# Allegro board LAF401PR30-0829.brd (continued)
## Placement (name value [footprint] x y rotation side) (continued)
PR603  0_0402_5%  [R0402_0OHM]  72.6 46.85 0 bottom
PR604  75_0402_1%  [R_0402]  73.76 49.92 0 bottom
PR605  100_0402_1%  [R_0402]  73.76 49.03 0 bottom
PR606  0_0402_5%  [R0402_0OHM]  69.42 88.41 180 bottom
PR608  88.7K_0402_1%  [R_0402]  73.42 47.11 270 top
PR610  10K_0402_1%  [R_0402]  72.22 56.15 270 top
PR611  1.87K +-1% 0402  [R_0402]  71.63 46.21 0 top
PR612  1.91K_0402_1%  [R_0402]  74.68 52.57 180 bottom
PR613  90.9K +-1% 0402  [R_0402]  71.25 52.34 90 bottom
PR614  0_0402_5%  [R0402_0OHM]  74.68 51.68 180 bottom
PR615  0_0402_5%  [R_0402]  64.2 55.19 90 top
PR616  0_0402_5%  [R0402_0OHM]  74.44 53.49 180 top
PR617  4.3K_0402_1%  [R_0402]  68.25 53.28 0 bottom
PR618  49.9_0402_1%  [R_0402]  74.63 50.82 180 top
PR619  2.2_0603_5%  [R_0603]  66.3 85.62 270 bottom
PR620  0_0402_5%  [R0402_0OHM]  73.1 55.63 270 top
PR621  316_0402_1%  [R_0402]  70.42 56.98 270 top
PR622  1.91K_0402_1%  [R_0402]  69.55 56.99 270 top
PR623  2K_0402_1%  [R_0402]  70.44 55.2 180 top
PR624  3.65K_0603_1%  [R_0603]  78.81 85.62 270 top
PR625  0_0402_5%  [R0402_0OHM]  74.43 49.92 180 top
PR626  10_0402_1%  [R_0402]  74.25 49.04 180 top
PR627  4.7_1206_5%  [R_1206]  76.97 86.06 180 top
PR628  4.99K_0402_1%  [R_0402]  69.52 56.09 0 bottom
PR629  88.7K_0402_1%  [R_0402]  66.5 51.8 180 bottom
PR630  2.49K_0402_1%  [R_0402]  70.84 47.2 0 bottom
PR631  27.4K_0402_1%  [R_0402]  71.3 57.4 0 top
PR632  1K_0402_1%  [R_0402]  66.88 56.98 180 top
PR633  11K_0402_1%  [R_0402]  67.77 55.18 90 bottom
PR634  0_0402_5%  [R_0402]  65.09 55.19 90 top
PR635  10K_0402_1%  [R_0402]  65.59 49.12 90 bottom
PR636  604_0402_1%  [R_0402]  71.77 43.9 0 top
PR638  374_0402_1%  [R_0402]  66.87 56.1 270 top
PR639  3.09K_0402_1%  [R_0402]  64.14 47.21 90 bottom
PR640  365_0402_1%  [R_0402]  62.8 47 180 top
PR641  1K_0402_1%  [R_0402]  73.57 44.79 270 top
PR642  2.61K_0402_1%  [R_0402]  81.4 83.01 0 top
PR643  11K_0402_1%  [R_0402]  72.67 43.05 270 top
PR644  1K_0402_1%  [R_0402]  61.03 46.09 90 top
PR645  316_0402_1%  [R_0402]  60.95 53.49 0 top
PR646  316_0402_1%  [R_0402]  67.1 43.83 270 bottom
PR647  27.4K_0402_1%  [R_0402]  66.47 50.03 270 bottom
PR648  1.91K_0402_1%  [R_0402]  62.74 51.82 90 top
PR649  1.62K_0402_1%  [R_0402]  67.08 44.68 0 bottom
PR650  2K_0402_1%  [R_0402]  62.74 53.6 90 top
PR651  113K_0402_1%  [R_0402]  68.06 47.07 90 bottom
PR652  2K_0402_1%  [R_0402]  66.24 44.7 270 bottom
PR653  20M_0402_5%  [R_0402]  60.01 50.89 270 top
PR656  11K_0402_1%  [R_0402]  61.04 48.76 270 top
PR657  4.42K_0402_1%  [R_0402]  60.17 49.1 180 top
PR658  20M_0402_5%  [R_0402]  68.65 56.1 270 bottom
PR659  0_0402_5%  [R0402_0OHM]  62.12 72.28 0 top
PR660  3.9_0603_1%  [R_0603]  53.59 71.04 0 bottom
PR661  3.65K_0603_1%  [R_0603]  58.7 48.05 0 top
PR662  0_0402_5%  [R0402_0OHM]  54.31 58.9 0 bottom
PR663  4.7_1206_5%  [R_1206]  64.69 71.52 270 top
PR664  0_0402_5%  [R0402_0OHM]  54.31 58.03 0 bottom
PR665  3.9_0603_1%  [R_0603]  54.37 61.66 0 bottom
PR666  10_0402_1%  [R_0402]  68.25 73.3 0 top
PR667  3.65K_0603_1%  [R_0603]  67.7 72.34 270 top
PR668  100K_0402_1%  [R_0402]  66.62 70.93 90 top
PR669  4.7_1206_5%  [R_1206]  67.02 66.95 180 top
PR670  100K_0402_1%  [R_0402]  71.3 58.29 0 top
PR671  0_0402_5%  [R_0402]  62.21 76.14 0 bottom
PR672  3.9_0603_1%  [R_0603]  63.06 77.62 0 top
PR673  10_0402_1%  [R_0402]  72.22 57.8 180 bottom
PR674  3.65K_0603_1%  [R_0603]  68.97 72.34 270 top
PR675  100K_0402_1%  [R_0402]  68.98 70 180 top
PR676  4.7_1206_5%  [R_1206]  71.76 78.43 270 top
PR677  100K_0402_1%  [R_0402]  68.98 69.11 180 top
PR678  100_0402_1%  [R_0402]  73.56 51.69 90 top
PR679  0_0402_5%  [R0402_0OHM]  68.22 83.58 180 bottom
PR680  1_0603_5%  [R_0603]  57.33 59.89 90 top
PR681  10K_0402_1%  [R_0402]  57.74 58.79 180 top
PR682  -  [SOLDER_PREFORMS_0603]  112.16 62.76 180 top
PR683  -  [SOLDER_PREFORMS_0603]  107.69 62.76 0 top
PR684  -  [SOLDER_PREFORMS_0603]  112.73 56.98 180 top
PR686  10K_0402_1%  [R_0402]  57.94 69.18 270 top
PR687  0_0402_5%  [R0402_0OHM]  57.18 68.27 90 top
PR688  1_0603_5%  [R_0603]  57.43 70.06 90 top
PR689  10K_0402_1%  [R_0402]  65.33 75.02 180 top
PR691  1_0603_5%  [R_0603]  64.44 76.24 180 top
PR692  0_0402_5%  [R_0402]  62.21 75.38 0 bottom
PR901  0.01_1206_1%  [R_1206_4P-D]  5.48 18.26 270 bottom
PR909  2_0603_1%  [R_0603]  14.06 22.09 0 top
PR910  2_0603_1%  [R_0603]  14.06 23.34 0 top
PR914  3.3_0603_1%  [R_0603]  19.56 21.93 90 top
PR915  4.7_0603_5%  [R_0603]  20.34 18.81 180 bottom
PR916  1_0805_5%~D  [R_0805]  12.29 21.8 180 top
PR917  0.005_1206_1%  [R_1206_4P-D]  29.74 11.13 270 top
PR918  100K_0402_1%  [R_0402]  12.37 19.58 0 bottom
PR919  0_0402_5%  [R_0402]  13.21 18.57 270 top
PR920  0_0402_5%  [R0402_0OHM]  12.29 16.73 0 top
PR921  4.7_0603_5%  [R_0603]  22.87 17.93 0 top
PR922  0_0402_5%  [R0402_0OHM]  12.29 15.84 0 top
PR923  4.7_1206_5%  [R_1206]  17.1 25.98 90 top
PR924  4.7_1206_5%  [R_1206]  28.45 23.7 0 top
PR925  154K_0402_1%  [R_0402]  33.66 32.58 90 top
PR926  0_0402_5%  [R0402_0OHM]  12.29 14.79 0 top
PR927  1M_0402_1%  [R_0402]  37.79 32.45 90 top
PR928  0_0402_5%  [R0402_0OHM]  12.29 13.92 0 top
PR929  0_0402_5%  [R0402_0OHM]  22.71 18.5 0 bottom
PR930  100K_0402_1%  [R_0402]  13.55 11.56 180 top
PR931  100K_0402_1%  [R_0402]  12.65 10.7 0 top
PR932  105K_0402_1%  [R_0402]  17.73 14.88 180 bottom
PR933  100K_0402_1%  [R_0402]  15.54 11.47 90 top
PR934  499_0402_1%  [R_0402]  16.4 12.39 270 top
PR935  0_0402_5%  [R0402_0OHM]  18.17 9.16 0 top
PR936  0_0402_5%  [R0402_0OHM]  19.11 12.39 270 top
PR937  1_0603_1%  [R_0603]  23.44 14.56 0 top
PR938  1_0603_1%  [R_0603]  23.44 13.3 0 top
PR939  0_0402_5%  [R0402_0OHM]  36.85 30.12 180 top
PR940  100_0402_5%  [R_0402]  21.87 11.49 90 top
PR941  0_0402_5%  [R0402_0OHM]  33.9 28.09 0 top
PR942  0_0402_5%  [R0402_0OHM]  34.37 31.64 180 top
PR943  0_0603_5%  [R_0603]  13.66 20.59 0 top
PR944  442K_0402_1%  [R_0402]  12.37 16.02 0 bottom
PR945  100K_0402_5%  [R_0402]  13.29 17.8 180 bottom
PR946  0_0402_5%  [R0402_0OHM]  30.03 33.36 0 top
PR947  0_0402_5%  [R0402_0OHM]  18.17 8.27 0 top
PR948  12.7K_0402_1%  [R_0402]  20.07 12.39 270 top
PR950  0_0402_5%  [R_0402]  32.52 28.86 270 top
PR951  0_0402_5%  [R0402_0OHM]  14.61 11.45 90 top
PR953  100K_0402_1%  [R_0402]  31.81 33.36 0 top
PR960  0_0402_5%  [R0402_0OHM]  12.32 18.57 270 top
PR961  100K_0402_1%  [R_0402]  31.63 29.94 270 top
PR1201  240K_0402_1%  [R_0402]  67.2 111.31 270 top
PR1202  300K_0402_5%  [R_0402]  4.2 39.23 90 top
PR1203  1.8M_0402_1%  [R_0402]  68.1 109.14 180 top
PR1205  499K_0402_1%  [R_0402]  7.75 51.58 270 top
PR1206  1K_0402_1%  [R_0402]  64.54 109.59 0 bottom
PR1207  499K_0402_1%  [R_0402]  9.39 41.72 0 top
PR1208  102K_0402_1%  [R_0402]  66.42 112.18 270 bottom
PR1209  100K_0402_5%  [R_0402]  3.22 40.12 270 top
PR1210  1M_0402_5%  [R_0402]  12.57 37.67 0 top
PR1211  0_0402_5%  [R0402_0OHM]  18.03 37.73 0 top
PR1212  49.9K_0402_1%  [R_0402]  3.64 49.36 180 top
PR1213  49.9K_0402_1%  [R_0402]  10.29 40.66 270 top
PR1214  100K_0402_5%  [R_0402]  18.3 31.83 180 top
PR1215  0_0402_5%  [R0402_0OHM]  23.25 33.93 90 top
PR1216  0_0402_5%  [R0402_0OHM]  17.15 33.63 180 top
PR1217  84.5K_0402_1%  [R_0402]  67.32 112.16 0 bottom
PR1218  0_0402_5%  [R0402_0OHM]  16.46 31.78 90 top
PR1219  23.2K_0402_1%  [R_0402]  68.07 111.27 0 top
PR1220  0_0402_5%  [R0402_0OHM]  16.21 37.61 180 top
PR1221  0_0402_5%  [R0402_0OHM]  21.34 34.44 0 top
PR1222  100K_0402_5%  [R_0402]  16.21 38.5 180 top
PR1223  0_0402_5%  [R0402_0OHM]  13.44 31.11 0 top
PR1224  100K_0402_5%  [R_0402]  22.23 35.32 90 top
PR1225  0_0402_5%  [R0402_0OHM]  21.19 30.88 0 top
PR1226  100K_0402_5%  [R_0402]  23.25 32.02 90 top
PR1227  100K_0402_5%  [R_0402]  16.64 85.11 270 top
PR1228  499K_0402_1%  [R_0402]  13.98 51.45 0 top
PR1229  49.9K_0402_1%  [R_0402]  15.93 52.29 90 top
PR1230  100K_0402_5%  [R_0402]  35.06 35.53 270 top
PR1231  100K_0402_5%  [R_0402]  32.14 35.72 270 top
PR1232  100K_0402_5%  [R_0402]  34.3 39.5 90 top
PR1233  100K_0402_5%  [R_0402]  31.25 35.72 270 top
PR1234  100K_0402_5%  [R_0402]  32.01 39.88 90 top
PR1235  100K_0402_5%  [R_0402]  31.12 39.88 90 top
PR1236  100K_0402_5%  [R_0402]  18.7 55.83 180 top
PR1237  100K_0402_1%  [R_0402]  69.24 103.04 90 bottom
PR1238  0_0402_5%  [R0402_0OHM]  68.65 105.44 180 top
PR1239  150K_0402_1%  [R_0402]  72.76 105.66 180 bottom
PR1240  100K_0402_1%  [R_0402]  67.54 103 90 top
PR1241  0_0402_5%  [R0402_0OHM]  33.27 35.51 0 top
PR1242  0_0402_5%  [R0402_0OHM]  30.36 34.8 90 top
PR1243  0_0402_5%  [R0402_0OHM]  66.61 103.91 270 top
PR1244  0_0402_5%  [R0402_0OHM]  65.46 108.65 180 bottom
PR1245  0_0402_5%  [R0402_0OHM]  28.34 37.61 180 top
PR1246  100K_0402_1%  [R_0402]  71.84 106.63 0 bottom
PR1247  100K_0402_1%  [R_0402]  68.36 103.95 270 bottom
PR1248  0_0402_5%  [R_0402]  69.92 110.26 0 top
PR1249  10K_0402_5%  [R_0402]  69.98 112.18 180 top
PR1250  0_0402_5%  [R0402_0OHM]  69.94 111.21 0 top
PR1251  300K_0402_5%  [R_0402]  3.17 55.01 0 top
PR1252  100K_0402_5%  [R_0402]  10.79 37.67 0 top
PR1253  100K_0402_5%  [R_0402]  11.05 33.55 0 top
PR1254  0_0402_5%  [R_0402]  18.04 38.63 0 top
PR1255  150K_0402_1%  [R_0402]  13.98 49.68 0 top
PR1257  0_0402_5%  [R0402_0OHM]  30.23 40.8 270 top
PR1258  0_0402_5%  [R_0402]  33.27 34.63 0 top
PR1259  100K_0402_5%  [R_0402]  26.5 30.82 180 top
PR1260  0_0402_5%  [R_0402]  27.49 34.69 0 top
PR1261  0_0402_5%  [R_0402]  28.4 33.74 180 top
PR1262  100K_0402_5%  [R_0402]  13.66 34.74 90 top
PRP1  100_0804_8P4R_5%  [RP_0804_8P4R]  19.45 5.54 90 top
PT1  PAD~D  [TPC12]  71.75 111.45 0 top
PU1  MC74VHC1G08DFT2G_SC70-5P  [TC7SH08FU_SSOP5]  65.25 96.09 270 bottom
PU2  RT9058-33GX SOT-89 3P LDO  [AP2204R-5P0TRG1_SOT89-3]  72.27 101.21 90 bottom
PU100  -  [SY8288BRAC_QFN20_3X3]  156.99 111.26 180 top
PU102  SYV828CRAC QFN 20P PWM  [SY8288CRAC_QFN20_3X3]  166.14 113.72 0 bottom
PU200  -  [SY8210AQVC_QFN19_4X3]  44.84 49.79 270 bottom
PU301  SY8286RAC_QFN20_3X3  [SY8288RAC_QFN20_3X3]  179.56 93.48 0 bottom
PU401  TPS62134CRGT_QFN16_3X3  [SY8057QDC_QFN16_3X3]  140.48 108.18 90 top
PU402  TPS62134DRGT_QFN16_3X3  [SY8057QDC_QFN16_3X3]  130.08 110.54 90 top
PU501  -  [RT8097ALGE_SOT23-6]  122.1 105.89 0 top
PU503  AP7361C-FGE-7-01_U-DFN3030-8_3X3  [AP7361C-FGE-7_U-DFN3030-8_3X3]  193.24 4.81 270 top
PU602  ISL95857AHRTZ-T TQFN 40P PWM  [ISL62883CHRTZ-T_TQFN40_5X5-S]  70.56 52.66 180 top
PU610  FDMF3035 PQFN 31P DR MOS  [NCP302045MNTWG_PQFN33_5X5]  57.35 69.03 90 bottom
PU612  FDMF3035 PQFN 31P DR MOS  [NCP302045MNTWG_PQFN33_5X5]  57.22 59.56 90 bottom
PU613  FDMF3035 PQFN 31P DR MOS  [NCP302045MNTWG_PQFN33_5X5]  64.56 75.56 90 bottom
PU614  ISL95808HRZ-TS2778 DFN MOSFET DRIVE  [ISL95808HRZ-TS2378_DFN8_2X2-S]  67.77 87.1 0 bottom
PU901  ISL9538HRTZ-T TQFN 32P PWM  [ISL88738HRTZ-T_TQFN32_4X4]  20.5 15.56 180 top
PU903  MC74VHC1G08DFT2G SC70 5P  [TC7SH08FU_SSOP5]  32.39 30.99 90 top
PU1200  MC74VHC1G08DFT2G SC70 5P  [TC7SH08FU_SSOP5]  18.79 36.64 180 top
PU1201  -  [LM393DGKR_VSSOP8]  66.92 109.73 270 bottom
QC2  -  [DMN65D8LDW-7_SOT363-6]  151.96 65.6 90 top
QC6  -  [L2N7002WT1G_SC-70-3]  179.01 35.26 90 top
QC7  -  [LP2301ALT1G_SOT23-3]  178.22 31.07 270 top
QE2  -  [DMN65D8LDW-7_SOT363-6]  298.22 61.93 180 top
QE3  -  [MMST3904-7-F_SOT323-3]  122.98 58.09 90 top
QE4  -  [MMST3904-7-F_SOT323-3]  284.1 72.92 90 top
QE5  -  [MMST3904-7-F_SOT323-3]  239.15 8.97 180 bottom
QE6  -  [MMST3904-7-F_SOT323-3]  78.75 48.66 180 top
QE7  -  [MMST3904-7-F_SOT323-3]  113.04 8.27 180 bottom
QE11  -  [L2N7002WT1G_SC-70-3]  280.04 70.44 180 top
QE12  -  [L2N7002WT1G_SC-70-3]  287.15 72.98 180 top
QE15  -  [LP2301ALT1G_SOT23-3]  320.49 63.48 180 top
QE17  -  [L2N7002WT1G_SC-70-3]  317.25 65.86 0 top
QL1  -  [DMN65D8LDW-7_SOT363-6]  283.15 97.67 90 top
QL2  -  [DMN65D8LDW-7_SOT363-6]  278.2 98.97 270 top
QN1  -  [DMN65D8LDW-7_SOT363-6]  281.18 38.5 90 top
QN4  DMN65D8LDW-7_SOT363-6  [DMN66D0LDW-7_SOT363-6]  208.73 35.72 270 top
QN5  DMN65D8LDW-7_SOT363-6  [DMN66D0LDW-7_SOT363-6]  223.84 34.17 90 top
QN6  -  [L2N7002WT1G_SC-70-3]  251.53 40.08 0 top
QN7  -  [L2N7002WT1G_SC-70-3]  248.93 39.51 0 top
QR1  -  [L2N7002WT1G_SC-70-3]  32.96 52.98 180 top
QT1  -  [DMN66D0LDW-7_SOT363-6]  37.39 81.05 0 top
QV1  -  [AO6405_TSOP6]  109.79 80.95 180 bottom
QV2  -  [L2N7002WT1G_SC-70-3]  102.17 81.99 90 bottom
QV3  -  [DMN65D8LDW-7_SOT363-6]  115 110.97 270 bottom
QV4  -  [L2N7002WT1G_SC-70-3]  111.13 103.21 180 top
QV5  -  [L2N7002WT1G_SC-70-3]  116.14 108.32 180 top
QV7  -  [L2N7002WT1G_SC-70-3]  120.91 83.84 180 bottom
QV8  -  [LP2301ALT1G_SOT23-3]  124.72 88.66 90 bottom
QZ1  -  [LP2301ALT1G_SOT23-3]  112.7 83.91 0 bottom
QZ2  -  [DMN65D8LDW-7_SOT363-6]  267.33 64.85 0 top
QZ3  DDTA114EUA-7-F_SOT323-3  [DDTA144VCA-7-F_SOT23-3]  269.58 73.68 180 top
QZ4  -  [L2N7002WT1G_SC-70-3]  317.44 71.39 0 top
QZ7  -  [DMN65D8LDW-7_SOT363-6]  315.71 97.49 0 bottom
QZ8  -  [L2N7002WT1G_SC-70-3]  292.49 67.02 90 top
QZ15  S TR BSS138W 1N SOT-323-3  [L2N7002WT1G_SC-70-3]  178.43 14.83 90 top
R274  0_0603_5%  [R0603_0OHM]  20.96 44.79 90 top
RA3  0_0603_5%  [R_0603]  302.65 42.5 90 top
RA5  2.2K_0402_5%  [R_0402]  310.22 38.12 180 bottom
RA6  2.2K_0402_5%  [R_0402]  310.22 37.17 180 bottom
RA7  16.2_0402_1%  [R_0402]  307.22 38.32 270 top
RA8  16.2_0402_1%  [R_0402]  307.09 35.63 90 top
RA9  33_0402_5%  [R_0402]  290.82 36.15 0 top
RA12  1K_0402_5%  [R_0402]  300.47 28.09 0 top
RA13  1K_0402_5%  [R_0402]  295.79 29.05 270 top
RA14  22_0402_5%  [R_0402]  292.6 37.99 0 top
RA17  33_0402_5%  [R_0402]  293.51 37.1 180 top
RA18  10K_0402_5%  [R_0402]  296.02 40.92 180 top
RA35  0_0402_5%  [R0402_0OHM]  308.36 42.68 90 top
RA36  0_0402_5%  [R0402_0OHM]  307.47 42.68 90 top
RA37  0_0402_5%  [R0402_0OHM]  294.47 29.04 180 top
RA44  100K_0402_5%  [R_0402]  306.89 32.15 0 top
RA45  10K_0402_5%  [R_0402]  297.69 29.05 270 top
RA48  0_0402_5%  [R0402_0OHM]  296.11 44.04 270 top
RA50  0_0402_5%  [R_0402]  296.87 41.34 90 top
RA51  10K_0402_5%  [R_0402]  298.71 29.05 270 top
RA52  100K_0402_5%  [R_0402]  292.36 38.88 0 top
RA53  0_0402_5%  [R_0402]  303.79 29.11 270 top
RA54  0_0402_5%  [R0402_0OHM]  302.9 29.11 270 top
RA57  4.7K_0402_5%  [R_0402]  305.37 36.52 45 top
RA58  4.7K_0402_5%  [R_0402]  305.37 35.25 45 top
RA59  100K_0402_1%  [R_0402]  293.62 31.9 0 top
RA60  200K_0402_1%  [R_0402]  294.45 30.83 270 top
RA61  100K_0402_1%  [R_0402]  296.22 30.8 0 top
RC1  100K_0402_5%  [R_0402]  132.42 62.5 180 top
RC2  24.9_0402_1%  [R_0402]  107.71 67.43 29.7 top
RC3  100_0402_1%  [R_0402]  129.16 78.05 90 top
RC4  200_0402_1%  [R_0402]  145.6 51.96 0 bottom
RC5  121_0402_1%  [R_0402]  130.94 42.83 270 top
RC6  80.6_0402_1%  [R_0402]  128.91 42.83 270 top
RC7  100_0402_1%  [R_0402]  129.93 42.83 270 top
RC10  1K_0402_1%  [R_0402]  166.83 47.36 90 top
RC11  1K_0402_1%  [R_0402]  161.46 49.81 270 top
RC12  1K_0402_5%  [R_0402]  148.67 65.1 180 top
RC14  1K_0402_5%  [R_0402]  153.34 67.01 0 top
RC15  1K_0402_5%  [R_0402]  147.43 62.76 0 bottom
RC16  15_0402_5%  [R_0402]  138.82 41.92 90 top
RC17  1K_0402_5%  [R_0402]  146.23 63.87 0 bottom
RC19  499_0402_1%  [R_0402]  150.12 59.33 0 bottom
RC20  499_0402_1%  [R_0402]  149.23 61.49 180 bottom
RC21  8.2K_0402_1%  [R_0402]  137.55 39.77 270 top
RC22  22_0402_5%  [R_0402]  142.5 36.72 270 top
RC23  2.2K_0402_5%  [R_0402]  144.4 63.72 0 top
RC25  4.7K_0402_5%  [R_0402]  145.6 61.46 0 bottom
RC27  8.2K_0402_5%  [R_0402]  138.44 39.77 270 top
RC28  33_0402_5%  [R_0402]  151.34 54.69 180 bottom
RC29  33_0402_5%  [R_0402]  152.02 64.41 270 bottom
RC30  1K_0402_5%  [R_0402]  162.44 58.17 90 bottom
RC31  1K_0402_5%  [R_0402]  156.6 61.12 270 top
RC32  0_0402_5%  [R_0402]  167.3 49.81 270 bottom
RC33  0_0402_5%  [R0402_0OHM]  166.29 49.81 270 bottom
RC34  0_0402_5%  [R0402_0OHM]  165.33 49.8 270 bottom
RC35  0_0402_5%  [R0402_0OHM]  163.81 49.8 270 bottom
RC36  0_0402_5%  [R0402_0OHM]  162.48 49.81 270 bottom
RC37  0_0402_5%  [R0402_0OHM]  162.69 66.36 90 bottom
RC38  0_0402_5%  [R0402_0OHM]  161.46 49.81 270 bottom
RC39  33_0402_5%  [R_0402]  162.69 63.82 90 bottom
RC40  0_0402_5%  [R0402_0OHM]  160.44 49.81 270 bottom
RC41  0_0402_5%  [R0402_0OHM]  159.43 48.9 90 bottom
RC42  0_0402_5%  [R_0402]  160.66 61.37 270 bottom
RC43  33_0402_5%  [R_0402]  162.44 57.12 270 bottom
RC44  113_0402_1%  [R_0402]  130.49 58.27 180 top
RC45  100_0402_1%  [R_0402]  131.75 67.96 0 top
RC46  1M_0402_1%  [R_0402]  116.6 78.5 180 bottom
RC47  10K_0402_5%  [R_0402]  146.56 36.72 270 top
RC48  1K_0402_5%  [R_0402]  133.74 39.78 270 top
RC50  10K_0402_5%  [R_0402]  137.03 42.82 0 top
RC51  10K_0402_5%  [R_0402]  145.67 33.68 270 top
RC52  2.7K_0402_1%  [R_0402]  124.66 61.47 90 top
RC54  10M_0402_5%  [R_0402]  151.52 42.18 0 bottom
RC56  20K_0402_5%  [R_0402]  135.77 39.78 270 top
RC57  20K_0402_5%  [R_0402]  154.63 52.36 270 bottom
RC59  10K_0402_5%  [R_0402]  149.36 36.73 270 top
RC60  0_0402_5%  [R_0402]  157.55 50.45 270 bottom
RC62  0_0402_5%  [R0402_0OHM]  161.02 52.05 90 bottom
RC65  100K_0402_5%  [R_0402]  155.78 50.37 180 bottom
RC67  1K_0402_5%  [R_0402]  132.21 36.34 270 top
RC68  10K_0402_5%  [R_0402]  135.13 30.76 270 top
RC69  1M_0402_5%  [R_0402]  135.77 36.98 90 top
RC71  1K_0402_5%  [R_0402]  97.67 79 90 bottom
RC72  8.2K_0402_5%  [R_0402]  150.75 33.67 270 top
RC73  10K_0402_5%  [R_0402]  151.77 33.67 270 top
RC74  10K_0402_5%  [R_0402]  145.36 36.23 270 top
RC75  10K_0402_5%  [R_0402]  132.85 39.77 270 top
RC77  1K_0402_5%  [R_0402]  90.24 81.16 270 bottom
RC78  60.4_0402_1%  [R_0402]  97.57 77.12 270 bottom
RC79  49.9_0402_1%  [R_0402]  101.61 75.46 90 bottom
RC80  1K_0402_5%  [R_0402]  99.7 79.01 90 bottom
RC81  51_0402_5%  [R_0402]  103.76 79 90 bottom
RC82  100_0402_5%  [R_0402]  105.8 79 90 bottom
RC83  1K_0402_5%  [R_0402]  93.66 80.24 90 bottom
RC84  499_0402_1%  [R_0402]  95.89 79.9 270 bottom
RC86  51_0402_5%  [R_0402]  104.91 75.46 90 bottom
RC87  1K_0402_5%  [R_0402]  101.73 79 90 bottom
RC88  49.9_0402_1%  [R_0402]  132.85 42.83 270 top
RC89  49.9_0402_1%  [R_0402]  131.96 42.83 270 top
RC90  49.9_0402_1%  [R_0402]  90.86 67.42 180 bottom
RC91  49.9_0402_1%  [R_0402]  90.86 66.41 180 bottom
RC92  33_0402_5%  [R_0402]  128.91 35.44 90 top
RC93  33_0402_5%  [R_0402]  127.02 36.4 180 top
RC94  33_0402_5%  [R_0402]  128.94 38.4 90 top
RC95  33_0402_5%  [R_0402]  128.02 34.61 90 top
RC96  200_0402_1%  [R_0402]  150.12 59.45 90 top
RC109  1K_0402_5%  [R_0402]  88.91 80.38 90 bottom
RC110  10K_0402_1%  [R_0402]  95.51 75.46 180 bottom
RC112  10K_0402_1%  [R_0402]  92.27 80.24 90 bottom
RC113  10K_0402_1%  [R_0402]  95.51 76.47 180 bottom
RC114  49.9_0402_1%  [R_0402]  103.26 66.58 180 top
RC115  1.5K_0402_5%  [R_0402]  130.82 86.25 180 top
RC120  100K_0402_5%  [R_0402]  98.68 79 90 bottom
RC121  0_0402_5%  [R_0402]  77.09 38.36 90 top
RC122  0_0402_5%  [R_0402]  76.08 38.36 90 top
RC123  1K_0402_5%  [R_0402]  67.95 39.27 270 top
RC124  1K_0402_5%  [R_0402]  68.97 39.27 270 top
RC126  1K_0402_5%  [R_0402]  73.54 38.36 90 top
RC128  0_0402_5%  [R_0402]  61.35 41.56 270 top
RC129  0_0402_5%  [R_0402]  62.36 41.56 270 top
RC130  51_0402_5%  [R_0402]  102.75 79 90 bottom
RC131  51_0402_5%  [R_0402]  51.19 29.3 270 top
RC132  150_0402_5%  [R_0402]  63.38 38.36 90 top
RC133  1.5K_0402_5%  [R_0402]  60.33 41.56 270 top
RC134  51_0402_5%  [R_0402]  51.69 35.82 90 top
RC135  100_0402_5%  [R_0402]  53.73 35.82 90 top
RC136  51_0402_5%  [R_0402]  54.23 29.3 270 top
RC137  3K_0402_5%  [R_0402]  62.87 27.59 270 top
RC138  51_0402_5%  [R_0402]  75.06 38.36 90 top
RC139  51_0402_5%  [R_0402]  61.35 38.36 90 top
RC140  100_0402_1%  [R_0402]  113.29 76.74 90 bottom
RC141  100_0402_1%  [R_0402]  114.16 76.74 90 bottom
RC143  0_0603_5%  [R0603_0OHM]  123.69 65.16 180 top
RC152  56_0402_1%  [R_0402]  99.7 76.71 90 bottom
RC153  220_0402_5%  [R_0402]  98.81 75.46 0 bottom
RC157  100_0402_1%  [R_0402]  98.68 76.71 90 bottom
RC161  100_0402_1%  [R_0402]  90.88 64.47 180 bottom
RC163  100_0402_1%  [R_0402]  90.86 65.44 180 bottom
RC165  100_0402_1%  [R_0402]  122.51 53.8 180 top
RC166  100_0402_1%  [R_0402]  121.16 80.39 90 top
RC167  100_0402_1%  [R_0402]  123.58 53.85 90 top
RC168  100_0402_1%  [R_0402]  122.43 81.3 270 top
RC169  0_0603_5%  [R0603_0OHM]  145.88 72.09 270 top
RC170  0_0402_5%  [R0402_0OHM]  125.46 81.16 270 top
RC171  0_0603_5%  [R_0603]  136.43 85.91 270 top
RC173  0_0402_5%  [R0402_0OHM]  126.37 80.41 180 bottom
RC175  2.2K_0402_5%  [R_0402]  140.09 88.97 90 top
RC176  2.2K_0402_5%  [R_0402]  121.35 83.91 90 top
RC177  2.2K_0402_5%  [R_0402]  120.34 83.91 90 top
RC178  2.2K_0402_5%  [R_0402]  139.07 88.97 90 top
RC183  8.2K_0402_5%  [R_0402]  148.34 36.72 270 top
RC184  8.2K_0402_5%  [R_0402]  149.74 39.85 270 top
RC186  4.7K_0402_5%  [R_0402]  148.72 33.68 270 top
RC187  4.7K_0402_5%  [R_0402]  130.94 39.77 270 top
RC189  10K_0402_5%  [R_0402]  147.71 33.68 270 top
RC190  10K_0402_5%  [R_0402]  141.86 38.89 270 top
RC211  0_0402_5%  [R_0402]  154.69 56.03 270 top
RC212  0_0402_5%  [R0402_0OHM]  155.58 56.03 270 top
RC214  0_0402_5%  [R_0402]  136.09 42.83 270 top
RC215  0_0402_5%  [R_0402]  131.83 38.88 90 top
RC216  0_0603_1%  [R0603_0OHM]  65.92 26.18 90 top
RC217  0_0402_5%  [R_0402]  63.38 41.56 270 top
RC218  150_0402_5%  [R_0402]  64.39 41.56 270 top
RC219  10K_0402_5%  [R_0402]  65.41 41.56 270 top
RC220  100K_0402_1%  [R_0402]  131.07 36.35 270 top
RC221  0_0402_5%  [R0402_0OHM]  278.77 92.02 90 bottom
RC222  1K_0402_5%  [R_0402]  279.79 92.02 90 bottom
RC223  1K_0402_5%  [R_0402]  129.82 38.4 90 top
RC224  1K_0402_5%  [R_0402]  148.16 88.47 180 bottom
RC225  8.2K_0402_5%  [R_0402]  151.39 90.81 90 bottom
RC227  8.2K_0402_5%  [R_0402]  151.39 89.44 270 bottom
RC228  0_0402_5%  [R0402_0OHM]  52.2 29.3 270 top
RC229  0_0402_5%  [R0402_0OHM]  52.71 35.82 90 top
RC230  0_0402_5%  [R0402_0OHM]  104.78 79.91 270 bottom
RC231  0_0402_5%  [R0402_0OHM]  112.29 53.87 180 top
RC234  0_0402_5%  [R_0402]  151.21 56.62 180 bottom
RC235  0_0402_5%  [R0402_0OHM]  151.21 56.85 180 top
RC237  10K_0402_5%  [R_0402]  150.35 54.88 0 top
RC239  0_0402_5%  [R_0402]  71.25 39.27 270 top
RC240  0_0402_5%  [R_0402]  70.24 39.27 270 top
RC241  1.5K_0402_5%  [R_0402]  64.9 38.36 90 top
RC243  10K_0402_5%  [R_0402]  133.36 31.26 270 top
RC244  0_0402_5%  [R0402_0OHM]  160.13 52.05 90 bottom
RC267  10K_0402_5%  [R_0402]  147.71 39.85 270 top
RC268  10K_0402_5%  [R_0402]  148.72 39.85 270 top
RC272  10K_0402_5%  [R_0402]  137.93 81.17 180 bottom
RC278  10K_0402_5%  [R_0402]  153.36 39.85 270 top
RC279  10K_0402_5%  [R_0402]  144.51 58.41 0 top
RC282  100K_0402_5%  [R_0402]  152.79 54.88 0 top
RC283  10K_0402_5%  [R_0402]  145.6 56.41 0 bottom
RC287  100K_0402_5%  [R_0402]  145.6 57.3 0 bottom
RC288  10K_0402_5%  [R_0402]  156.15 76.21 90 bottom
RC290  0_0402_5%  [R0402_0OHM]  150.2 88.47 180 bottom
RC291  10K_0402_5%  [R_0402]  146.31 89.79 90 bottom
RC292  10K_0402_5%  [R_0402]  133.61 86.51 270 top
RC294  0_0402_5%  [R0402_0OHM]  115.69 79.39 0 bottom
RC295  0_0402_5%  [R0402_0OHM]  117.47 79.39 0 bottom
RC296  0_0402_5%  [R0402_0OHM]  150.63 42.18 90 bottom
RC297  0_0402_5%  [R_0402]  112.38 76.74 90 bottom
RC298  0_0402_5%  [R_0402]  111.49 76.74 90 bottom
RC299  0_0603_5%  [R0603_0OHM]  133.74 82.06 270 bottom
RC300  0_0402_5%  [R0402_0OHM]  138.51 85.62 180 top
RC301  0_0402_5%  [R0402_0OHM]  144.4 66.54 90 top
RC302  0_0402_5%  [R0402_0OHM]  132.59 86.25 180 top
RC303  0_0402_5%  [R0402_0OHM]  128.26 80.9 270 top
RC304  0_0402_5%  [R0402_0OHM]  145.42 59.58 180 top
RC305  0_0402_5%  [R0402_0OHM]  131.17 55.72 180 top
RC306  0_0402_5%  [R0402_0OHM]  151.25 57.73 180 top
RC307  0_0402_5%  [R0402_0OHM]  145.42 57.55 180 top
RC308  0_0402_5%  [R0402_0OHM]  145.42 60.47 180 top
RC309  0_0603_5%  [R0603_0OHM]  120.08 80.09 180 top
RC310  0_0603_5%  [R0603_0OHM]  144.59 71.65 90 top
RC311  10K_0402_5%  [R_0402]  133.99 42.83 270 top
RC313  0_0402_5%  [R_0402]  145.31 69.79 180 top
RC316  1K_0402_5%  [R_0402]  155.58 61.12 270 top
RC317  150K_0402_5%  [R_0402]  148.66 55.66 270 bottom
RC318  2.2K_0402_5%  [R_0402]  148.67 67.01 180 top
RC319  2.2K_0402_5%  [R_0402]  153.34 65.99 0 top
RC323  10K_0402_5%  [R_0402]  143.64 33.68 270 top
RC324  59_0402_1%  [R_0402]  113.52 67.24 270 top
RC325  0_0402_5%  [R0402_0OHM]  156.66 50.45 270 bottom
RC328  0_0402_5%  [R0402_0OHM]  101.58 78 0 bottom
RC330  49.9K_0402_1%  [R_0402]  145.6 52.85 0 bottom
RC331  49.9K_0402_1%  [R_0402]  145.6 55.52 0 bottom
RC337  10K_0402_5%  [R_0402]  151.77 36.8 270 top
RC338  1K_0402_5%  [R_0402]  150.75 39.85 270 top
RC344  10K_0402_5%  [R_0402]  136.15 30.76 270 top
RC345  100K_0402_5%  [R_0402]  144.39 68.97 0 top
RC346  10K_0402_5%  [R_0402]  151.9 75.41 270 bottom
RC347  499_0402_1%  [R_0402]  150.12 60.22 0 bottom
RC348  499_0402_1%  [R_0402]  150.12 61.49 0 bottom
RC349  100_0402_1%  [R_0402]  140.09 39.77 270 top
RC362  1K_0402_5%  [R_0402]  147.96 54.76 0 top
RC363  1K_0402_5%  [R_0402]  147.96 55.64 0 top
RC366  15_0402_5%  [R_0402]  138.69 36.72 270 top
RC367  15_0402_5%  [R_0402]  139.58 36.72 270 top
RC368  15_0402_5%  [R_0402]  136.66 39.77 270 top
RC369  15_0402_5%  [R_0402]  140.59 36.72 270 top
RC370  10K_0402_5%  [R_0402]  151.64 39.85 270 top
RC371  10K_0402_5%  [R_0402]  147.35 65.8 0 bottom
RC372  10K_0402_5%  [R_0402]  146.61 65.8 180 bottom
RC373  0_0402_5%  [R0402_0OHM]  146.69 33.68 270 top
RC374  0_0402_5%  [R0402_0OHM]  147.45 36.72 270 top
RC376  0_0402_5%  [R0402_0OHM]  150.37 36.73 270 top
RC377  0_0402_5%  [R0402_0OHM]  144.66 33.68 270 top
RC378  0_0402_5%  [R0402_0OHM]  140.98 38.88 270 top
RC387  10K_0402_5%  [R_0402]  149.74 33.68 270 top
RC400  10K_0402_5%  [R_0402]  147.35 66.69 0 bottom
RC401  10K_0402_5%  [R_0402]  146.61 66.69 180 bottom
RC402  49.9K_0402_1%  [R_0402]  145.6 53.74 0 bottom
RC403  49.9K_0402_1%  [R_0402]  145.6 54.63 0 bottom
RC404  10K_0402_5%  [R_0402]  144.39 68.19 0 top
RC405  100K_0402_5%  [R_0402]  145.6 58.16 0 bottom
RC407  33_0402_5%  [R_0402]  156.66 61.37 270 bottom
RC408  33_0402_5%  [R_0402]  157.61 61.37 270 bottom
RC409  33_0402_5%  [R_0402]  158.63 61.37 270 bottom
RC410  33_0402_5%  [R_0402]  159.64 61.37 270 bottom
RC411  10K_0402_5%  [R_0402]  125.16 36.42 270 top
RC413  10K_0402_5%  [R_0402]  141.1 88.97 90 top
RC414  10K_0402_5%  [R_0402]  140.85 42.83 270 top
RC417  33_0402_5%  [R_0402]  142.85 73.86 0 bottom
RC418  33_0402_5%  [R_0402]  142.85 74.74 0 bottom
RC419  33_0402_5%  [R_0402]  116.6 77.62 180 bottom
RC420  33_0402_5%  [R_0402]  118.38 78.5 180 bottom
RC421  1M_0402_1%  [R_0402]  144.66 74.74 270 bottom
RC422  0_0402_5%  [R0402_0OHM]  144.66 75.58 90 bottom
RC431  100K_0402_5%  [R_0402]  182.06 34.57 270 top
RC432  499K_0402_1%  [R_0402]  180.61 33.55 180 top
RC433  49.9K_0402_1%  [R_0402]  178.95 33.55 180 top
RC436  0_0402_5%  [R_0402]  101.68 67.96 180 top
RC437  0_0402_5%  [R_0402]  105.75 67.94 0 top
RC438  0_0402_5%  [R_0402]  107.38 55.06 90 top
RC439  0_0402_5%  [R0402_0OHM]  176.52 32.59 0 top
RC440  0_0402_5%  [R_0402]  174.07 30.5 180 top
RC441  0_0402_5%  [R0402_0OHM]  183.89 32.66 0 top
RC442  0_0402_5%  [R_0402]  183.89 33.61 0 top
RC443  0_0402_5%  [R_0402]  144.34 36.71 90 top
RC444  0_0402_5%  [R0402_0OHM]  145.36 37.09 90 top
RC445  0_0402_5%  [R0402_0OHM]  182.06 36.35 270 top
RC550  0_0402_5%  [R0402_0OHM]  145.55 74.74 270 bottom
RC551  1K_0402_5%  [R_0402]  131.32 53.66 180 top
RC553  10K_0402_5%  [R_0402]  145.6 59.84 0 bottom
RC554  10K_0402_5%  [R_0402]  146.51 59.02 180 bottom
RC555  10K_0402_5%  [R_0402]  147.35 64.92 0 bottom
RC556  10K_0402_5%  [R_0402]  146.61 64.92 180 bottom
RC560  0_0402_5%  [R_0402]  160.28 41.7 90 top
RC561  0_0402_5%  [R_0402]  159.39 42.03 90 top
RD4  0_0402_5%  [R_0402]  103.64 3.05 90 top
RD5  0_0402_5%  [R0402_0OHM]  102.62 3.97 270 top
RD6  0_0402_5%  [R_0402]  104.65 3.05 90 top
RD7  0_0402_5%  [R0402_0OHM]  105.67 3.97 270 top
RD8  0_0402_5%  [R_0402]  88.52 2.29 90 top
RD9  0_0402_5%  [R0402_0OHM]  88.52 4.32 90 top
RD10  0_0603_5%  [R0603_0OHM]  106.13 7.56 180 top
RD11  470_0402_1%  [R_0402]  64.9 4.22 270 top
RD12  0_0402_5%  [R0402_0OHM]  65.92 4.22 270 top
RD14  1K_0402_5%  [R_0402]  73.03 4.32 90 top
RD15  1K_0402_1%  [R_0402]  86.7 5.29 180 top
RD16  1K_0402_1%  [R_0402]  85.78 4.27 0 top
RD17  2_0402_1%  [R_0402]  83.95 5.24 270 top
RD18  24.9_0402_1%  [R_0402]  85.78 3.25 0 top
RD19  100K_0402_5%  [R_0402]  65.66 18.7 270 top
RD20  0_0402_5%  [R_0402]  186.19 2.29 90 top
RD21  0_0402_5%  [R0402_0OHM]  187.14 3.21 270 top
RD22  0_0402_5%  [R0402_0OHM]  189.04 2.29 90 top
RD23  0_0402_5%  [R_0402]  188.09 3.21 270 top
RD24  0_0402_5%  [R_0402]  169.69 2.49 180 top
RD25  0_0402_5%  [R0402_0OHM]  168.78 3.45 0 top
RD26  0_0603_5%  [R0603_0OHM]  187.79 13.52 270 top
RD27  1K_0402_5%  [R_0402]  141.46 2.49 180 top
RD28  1K_0402_1%  [R_0402]  171.48 5.31 270 top
RD29  1K_0402_1%  [R_0402]  170.46 4.4 90 top
RD30  2_0402_1%  [R_0402]  171.2 3.2 270 top
RD31  24.9_0402_1%  [R_0402]  173.23 3.2 270 top
RE5  10K_0402_5%  [R_0402]  298.52 83.93 90 top
RE8  100K_0402_5%  [R_0402]  304.81 83.84 90 top
RE10  100K_0402_5%  [R_0402]  299.32 83.81 90 top
RE11  100K_0402_5%  [R_0402]  296.49 69.38 270 top
RE12  100K_0402_5%  [R_0402]  308.11 65.93 270 top
RE20  100K_0402_5%  [R_0402]  307.59 70 0 top
RE21  10K_0402_5%  [R_0402]  299.09 64.46 90 top
RE25  100K_0402_5%  [R_0402]  307.46 85.04 0 top
RE26  10_0402_5%  [R_0402]  308.55 86.84 270 top
RE30  0_0402_5%  [R0402_0OHM]  274.15 78.44 180 bottom
RE31  100K_0402_5%  [R_0402]  286.9 69.92 90 top
RE32  0_0402_5%  [R0402_0OHM]  289.26 77.92 0 top
RE33  1K_0402_5%  [R_0402]  285.88 70.83 270 top
RE35  10K_0402_5%  [R_0402]  306.58 84.14 90 top
RE37  2.2K_0402_5%  [R_0402]  307.4 71.77 0 top
RE38  10K_0402_5%  [R_0402]  305.69 84.14 90 top
RE43  2.2K_0402_5%  [R_0402]  307.4 70.88 0 top
RE48  10K_0402_5%  [R_0402]  270.39 41.5 270 bottom
RE51  10K_0402_5%  [R_0402]  268.43 43.58 180 top
RE55  100K_0402_5%  [R_0402]  293.79 69.67 270 top
RE56  10K_0402_5%  [R_0402]  302.76 68.8 270 top
RE57  1K_0402_5%  [R_0402]  295.58 69.41 270 top
RE58  100K_0402_5%  [R_0402]  294.69 69.67 270 top
RE59  0_0402_5%  [R0402_0OHM]  305.65 87.43 270 top
RE60  43_0402_5%  [R_0402]  302.71 83.8 90 top
RE63  100K_0402_5%  [R_0402]  301 87.13 90 top
RE64  300_0402_5%  [R_0402]  304.82 68 270 top
RE65  100_0402_1%  [R_0402]  300.39 86.05 180 top
RE67  10K_0402_5%  [R_0402]  297.06 62.93 90 top
RE68  100K_0402_5%  [R_0402]  297.64 58.95 180 top
RE69  8.2K_0402_5%  [R_0402]  284.41 74.19 0 top
RE70  2.2K_0402_5%  [R_0402]  279.58 73.68 0 top
RE71  10_0402_1%  [R_0402]  273.23 79.46 0 bottom
RE72  10K_0402_5%  [R_0402]  273.23 77.42 0 bottom
RE73  10K_0402_5%  [R_0402]  273.23 73.36 0 bottom
RE74  10K_0402_5%  [R_0402]  273.23 72.34 0 bottom
RE75  100K_0402_5%  [R_0402]  273.23 75.39 0 bottom
RE77  1.69K_0402_1%  [R_0402]  293.32 82.57 180 top
RE79  4.3K_0402_5%  [R_0402]  303.79 83.84 90 top
RE83  100K_0402_5%  [R_0402]  301.95 87.13 90 top
RE84  100K_0402_5%  [R_0402]  300.74 92.78 90 top
RE85  100K_0402_5%  [R_0402]  299.73 92.78 90 top
RE86  10K_0402_5%  [R_0402]  274.15 76.41 180 bottom
RE90  0_0402_5%  [R0402_0OHM]  280.5 74.69 180 top
RE91  100K_0402_5%  [R_0402]  304.06 89.43 180 top
RE92  100K_0402_5%  [R_0402]  289.36 68.6 0 top
RE93  100K_0201_5%  [R_0201]  287.71 76.94 270 top
RE94  75_0402_5%  [R_0402]  287.2 71.77 0 top
RE95  100K_0402_5%  [R_0402]  311.23 78.38 180 top
RE274  0_0402_5%  [R_0402]  309.38 66.36 90 top
RE275  0_0402_5%  [R0402_0OHM]  310.25 66.38 0 top
RE280  0_0402_5%  [R_0402]  305.64 96.03 180 top
RE288  100_0402_5%  [R_0402]  301.38 83.76 90 top
RE290  0_0402_5%  [R0402_0OHM]  293.26 73.12 270 top
RE292  0_0402_5%  [R_0402]  303.61 96.03 180 top
RE300  33K_0402_5%  [R_0402]  300.61 88.97 90 top
RE301  10K_0402_5%  [R_0402]  293.25 83.46 180 top
RE302  2.2K_0402_5%  [R_0402]  289.84 74.26 0 top
RE303  2.2K_0402_5%  [R_0402]  289.84 73.47 0 top
RE304  0_0402_5%  [R_0402]  308.49 93.54 90 top
RE306  0_0402_5%  [R_0402]  273.23 74.38 0 bottom
RE308  0_0402_5%  [R_0402]  306.66 87.43 270 top
RE312  300_0402_5%  [R_0402]  310.25 67.71 0 top
RE313  10K_0402_5%  [R_0402]  310.25 68.6 0 top
RE314  100_0402_1%  [R_0402]  299.94 67.57 0 top
RE318  0_0402_5%  [R0402_0OHM]  296.6 64.87 0 top
RE324  100K_0402_5%  [R_0402]  292.13 68.73 180 top
RE340  10K_0402_5%  [R_0402]  268.09 75.77 0 bottom
RE342  10K_0402_5%  [R_0402]  307.46 74.5 0 top
RE343  240K_0402_5%  [R_0402]  298.01 66.62 90 top
RE349  43K_0402_1%  [R_0402]  308.31 73.55 180 top
RE350  33_0402_5%  [R_0402]  285.83 78.48 180 top
RE361  49.9K_0402_1%  [R_0402]  297.13 66.63 180 top
RE362  100K_0402_5%  [R_0402]  297.13 67.52 180 top
RE365  100K_0402_5%  [R_0402]  297.57 83.83 90 top
RE375  0_0402_5%  [R_0402]  267.98 67 90 bottom
RE505  100K_0402_5%  [R_0402]  269.49 91.02 90 top
RE507  100K_0402_5%  [R_0402]  290.56 75.05 180 top
RE508  100K_0402_5%  [R_0402]  287.33 68.6 0 top
RE524  2.2K_0402_5%  [R_0402]  283.35 75.84 180 top
RE525  2.2K_0402_5%  [R_0402]  283.35 76.79 180 top
RE526  10K_0402_5%  [R_0402]  299.33 90 0 bottom
RE532  4.7K_0402_5%  [R_0402]  301.96 90 180 bottom
RE536  0_0402_5%  [R0402_0OHM]  284.93 75.89 90 top
RE539  100_0402_5%  [R_0402]  306.67 91.48 0 top
RE541  100K_0402_5%  [R_0402]  315.73 61.94 270 top
RE543  1M_0402_5%  [R_0402]  316.68 61.94 270 top
RE546  10K_0402_5%  [R_0402]  320.31 65.23 180 top
RE547  100K_0402_5%  [R_0402]  310.32 77.42 0 top
RE548  0_0402_5%  [R0402_0OHM]  301.95 67.89 90 top
RE549  100K_0402_5%  [R_0402]  308.5 68.22 180 top
RE550  100K_0402_5%  [R_0402]  307.59 69.11 0 top
RE551  0_0402_5%  [R_0402]  321.62 64.22 0 bottom
RE552  0_0402_5%  [R0402_0OHM]  179.08 13.12 180 top
RE560  0_0402_5%  [R_0402]  287.46 77.17 0 bottom
RE561  100K_0402_5%  [R_0402]  307.4 72.66 0 top
RE565  0_0402_5%  [R_0402]  286.85 77.69 0 top
RI13  10K_0402_5%  [R_0402]  305.69 62.5 180 top
RI14  22.1K_0402_1%  [R_0402]  311.79 61.94 270 top
RI27  0_0402_5%  [R_0402-NPM]  292.49 45.43 270 top
RI28  0_0402_5%  [R_0402-NPM]  291.47 45.43 270 top
RI29  0_0402_5%  [R_0402-NPM]  295.6 47.4 270 top
RI30  0_0402_5%  [R_0402-NPM]  294.71 47.4 270 top
RI34  4.7K_0402_5%  [R_0402]  303.66 61.44 270 top
RI35  0_0402_5%  [R_0402]  296.85 53.61 0 top
RI36  4.99K_0402_1%  [R_0402]  305.06 54.4 90 top
RI37  2K_0402_5%  [R_0402]  303.93 51.77 180 top
RI38  4.7K_0402_5%  [R_0402]  302.65 62.68 90 top
RI39  4.7K_0402_5%  [R_0402]  302.65 60.52 90 top
RI40  4.7K_0402_5%  [R_0402]  300.61 62.68 90 top
RI41  4.7K_0402_5%  [R_0402]  300.61 60.52 90 top
RI42  4.7K_0402_5%  [R_0402]  302.07 52.67 270 top
RI43  4.7K_0402_5%  [R_0402]  302.2 50.32 270 top
RI44  4.7K_0402_5%  [R_0402]  300.23 52.67 270 top
RI45  4.7K_0402_5%  [R_0402]  300.42 50.32 270 top
RI47  0_0402_5%  [R_0402-NPM]  290.45 45.43 270 top
RI48  0_0402_5%  [R_0402-NPM]  289.44 45.43 270 top
RI49  0_0402_5%  [R_0402-NPM]  196.72 24.4 0 bottom
RI50  0_0402_5%  [R_0402-NPM]  196.72 23.39 0 bottom
RI51  4.7K_0402_5%  [R_0402]  299.6 62.68 90 top
RI52  4.7K_0402_5%  [R_0402]  299.6 60.52 90 top
RI53  4.7K_0402_5%  [R_0402]  301.63 62.68 90 top
RI54  4.7K_0402_5%  [R_0402]  301.63 60.52 90 top
RI55  4.7K_0402_5%  [R_0402]  306.67 51.08 270 top
RI56  4.7K_0402_5%  [R_0402]  305.78 51.08 270 top
RI57  4.7K_0402_5%  [R_0402]  301.12 52.67 270 top
RI58  4.7K_0402_5%  [R_0402]  301.31 50.32 270 top
RI79  0_0603_5%  [R_0603]  315.54 68.22 180 top
RI80  0_0603_5%  [R0603_0OHM]  315.54 69.49 180 top
RI81  0_0402_5%  [R0402_0OHM]  303.93 52.66 180 top
RL1  10K_0402_5%  [R_0402]  273.13 84.09 180 top
RL2  10K_0402_5%  [R_0402]  273.13 82.57 180 top
RL3  0_0402_5%  [R0402_0OHM]  283.39 84.98 0 top
RL4  4.7K_0402_5%  [R_0402]  279.38 80.5 270 top
RL5  10K_0402_5%  [R_0402]  280.4 80.49 270 top
RL6  4.7K_0402_5%  [R_0402]  283.09 80.47 270 top
RL7  0_0402_5%  [R0402_0OHM]  282.21 79.57 90 top
RL8  0_0603_5%  [R0603_0OHM]  283.53 81.68 0 top
RL9  10K_0402_5%  [R_0402]  281.31 80.49 270 top
RL11  1M_0402_5%  [R_0402]  285.37 89.35 90 top
RL12  1K_0402_5%  [R_0402]  273.13 85.11 180 top
RL13  3.01K_0402_1%  [R_0402]  283.34 89.35 90 top
RL14  150_0402_5%  [R_0402]  279.21 100.53 90 top
RL15  75_0402_1%  [R_0402]  292.99 101.31 270 top
RL16  75_0402_1%  [R_0402]  295.53 101.31 270 top
RL17  75_0402_1%  [R_0402]  298.84 101.31 270 top
RL18  75_0402_1%  [R_0402]  302.39 101.31 270 top
RL19  150_0402_5%  [R_0402]  280.17 100.53 90 top
RL20  150_0402_5%  [R_0402]  282.38 100.48 0 top
RL29  1M_0402_5%  [R_0402]  281.31 101.44 270 top
RL30  1M_0402_5%  [R_0402]  278.26 101.44 270 top
RL34  0_0402_5%  [R0402_0OHM]  285.32 88.16 180 top
RL70  10K_0402_5%  [R_0402]  142.63 33.68 270 top
RL71  2.2_0603_5%  [R_0603]  283.6 91.78 90 top
RL72  2.2_0603_5%  [R_0603]  282.33 91.78 90 top
RL73  2.2_0603_5%  [R_0603]  281.06 91.78 90 top
RL74  2.2_0603_5%  [R_0603]  279.79 91.78 90 top
RL75  2.2_0603_5%  [R_0603]  278.52 91.78 90 top
RL76  2.2_0603_5%  [R_0603]  277.25 91.78 90 top
RL77  2.2_0603_5%  [R_0603]  275.98 91.78 90 top
RL78  2.2_0603_5%  [R_0603]  274.71 91.78 90 top
RN1  100K_0402_5%  [R_0402]  282.26 40.58 90 bottom
RN2  100K_0402_5%  [R_0402]  277.75 38.04 90 top
RN3  10K_0402_5%  [R_0402]  276.48 36.72 90 bottom
RN4  10K_0402_5%  [R_0402]  276.36 40.14 90 bottom
RN5  10K_0402_5%  [R_0402]  276.36 41.92 90 bottom
RN6  4.7K_0402_5%  [R_0402]  271.96 62.76 0 top
RN7  4.7K_0402_5%  [R_0402]  272.04 62.25 0 bottom
RN8  4.7K_0402_5%  [R_0402]  272.88 63.77 180 top
RN9  4.7K_0402_5%  [R_0402]  272.04 63.14 0 bottom
RN10  4.7K_0402_5%  [R_0402]  280.68 62.38 0 top
RN11  4.7K_0402_5%  [R_0402]  278.14 62.38 0 bottom
RN12  4.7K_0402_5%  [R_0402]  281.56 64.53 180 top
RN13  4.7K_0402_5%  [R_0402]  276.23 63.26 0 bottom
RN14  4.7K_0402_5%  [R_0402]  271.96 64.79 0 top
RN15  7.87K_0402_1%  [R_0402]  272.04 64.03 0 bottom
RN16  4.7K_0402_5%  [R_0402]  281.56 60.98 180 top
RN17  4.7K_0402_5%  [R_0402]  278.14 61.49 0 bottom
RN18  4.7K_0402_5%  [R_0402]  279.41 58.62 90 top
RN19  4.7K_0402_5%  [R_0402]  278.45 59.53 270 top
RN20  4.7K_0402_5%  [R_0402]  281.56 63.65 180 top
RN21  4.7K_0402_5%  [R_0402]  279.02 63.26 180 bottom
RN25  10K_0402_5%  [R_0402]  258.83 42.23 90 top
RN26  10K_0402_5%  [R_0402]  260.74 42.11 90 top
RN27  10K_0402_5%  [R_0402]  268.43 44.53 180 top
RN28  10K_0402_5%  [R_0402]  261.69 42.11 90 top
RN30  4.99K_0402_1%  [R_0402]  263.59 43.02 270 top
RN31  4.99K_0402_1%  [R_0402]  294.25 55.33 0 top
RN37  10K_0402_5%  [R_0402]  294 27.77 0 top
RN38  10K_0402_5%  [R_0402]  259.54 44.47 180 top
RN39  10K_0402_5%  [R_0402]  259.78 43.02 270 top
RN40  10K_0402_5%  [R_0402]  267.52 45.48 0 top
RN41  10K_0402_5%  [R_0402]  262.64 43.02 270 top
RN42  10K_0402_5%  [R_0402]  261.75 51.91 270 top
RN43  10K_0402_5%  [R_0402]  261.75 53.15 90 top
RN44  10K_0402_5%  [R_0402]  265.44 52.04 270 top
RN49  10K_0402_5%  [R_0402]  265.5 42.11 90 top
RN50  10K_0402_5%  [R_0402]  264.55 52.04 270 top
RN51  10K_0402_5%  [R_0402]  268.43 47.52 180 top
RN52  10K_0402_5%  [R_0402]  264.55 43.02 270 top
RN53  10K_0402_5%  [R_0402]  263.66 51.12 90 top
RN54  10K_0402_5%  [R_0402]  267.52 46.5 0 top
RN55  10K_0402_5%  [R_0402]  292.74 52.49 270 bottom
RN56  10K_0402_5%  [R_0402]  295.15 52.34 180 top
RN57  10K_0402_5%  [R_0402]  293.2 59.71 180 bottom
RN58  10K_0402_5%  [R_0402]  295.17 53.29 180 top
RN59  10K_0402_5%  [R_0402]  291.85 51.58 90 bottom
RN60  10K_0402_5%  [R_0402]  294.26 51.45 0 top
RN61  10K_0402_5%  [R_0402]  292.28 60.66 0 bottom
RN62  10K_0402_5%  [R_0402]  294.25 54.31 0 top
RN63  10K_0402_5%  [R_0402]  226.14 35.83 180 top
RN64  10K_0402_5%  [R_0402]  219.64 32.28 0 top
RN65  10K_0402_5%  [R_0402]  209.68 32.39 90 top
RN69  10K_0402_5%  [R_0402]  295.17 57.23 180 top
RN70  10K_0402_5%  [R_0402]  288.31 56.6 180 bottom
RN71  10K_0402_5%  [R_0402]  290.96 57.93 180 bottom
RN72  10K_0402_5%  [R_0402]  294.25 56.28 0 top
RN73  10K_0402_5%  [R_0402]  287.39 55.71 0 bottom
RN74  10K_0402_5%  [R_0402]  289.18 57.93 180 bottom
RN77  0_0402_5%  [R0402_0OHM]  286.28 39.13 180 bottom
RN78  0_0402_5%  [R0402_0OHM]  286.28 38.25 180 bottom
RN81  0_0402_5%  [R0402_0OHM]  283.67 42.44 180 bottom
RN82  0_0402_5%  [R0402_0OHM]  283.67 43.33 180 bottom
RN99  0_0402_5%  [R0402_0OHM]  292.22 27.77 0 top
RN100  0_0402_5%  [R_0402]  253.05 24.16 270 bottom
RN101  0_0402_5%  [R_0402]  253.94 24.16 270 bottom
RN171  100K_0402_5%  [R_0402]  212.67 34.93 90 top
RN174  10K_0402_5%  [R_0402]  266.32 51.12 90 top
RN176  10K_0402_5%  [R_0402]  262.64 54.07 270 top
RN179  10K_0402_5%  [R_0402]  262.64 51 90 top
RN182  0_0402_5%  [R_0402]  209.29 36.85 0 top
RN183  100K_0402_5%  [R_0402]  211.71 34 270 top
RN184  0_0402_5%  [R_0402]  226.14 33.8 180 top
RN185  100K_0402_5%  [R_0402]  225.23 32.78 0 top
RN186  0_0402_5%  [R0402_0OHM]  226.14 31.77 180 top
RN187  0_0402_5%  [R0402_0OHM]  219.64 35.32 0 top
RN188  100K_0402_5%  [R_0402]  220.55 36.34 180 top
RN189  0_0402_5%  [R_0402]  219.64 34.31 0 top
RN192  0_0402_5%  [R0402_0OHM]  211.71 35.84 270 top
RN223  0_0402_5%  [R0402_0OHM]  208.73 33.3 270 top
RN224  0_0402_5%  [R0402_0OHM]  220.55 33.29 180 top
RN225  0_0402_5%  [R0402_0OHM]  225.23 34.82 0 top
RN226  4.7K_0402_5%  [R_0402]  250.64 42.13 270 top
RN227  0_0402_5%  [R_0402]  251.53 41.22 90 top
RN228  4.7K_0402_5%  [R_0402]  249.12 41.5 270 top
RN229  0_0402_5%  [R_0402]  247.34 41.5 270 top
RN230  0_0402_5%  [R_0402]  248.23 41.5 270 top
RPC1  33_0804_8P4R_5%  [RP_0804_8P4R]  154.67 60.38 90 bottom
RPC3  10K_8P4R_5%  [RP_0804_8P4R]  136.28 79.27 270 bottom
RPC4  10K_8P4R_5%  [RP_0804_8P4R]  145.99 69.43 0 bottom
RPE7  10K_8P4R_5%  [RP_0804_8P4R]  274.27 82.24 180 bottom
RPE9  100K_0804_8P4R_5%  [RP_0804_8P4R]  310.18 81.02 0 top
RPE10  100K_0804_8P4R_5%  [RP_0804_8P4R]  306.98 88.85 90 top
RPE11  100K_0804_8P4R_5%  [RP_0804_8P4R]  305.68 65.79 270 top
RPE12  2.2K_0804_8P4R_5%  [RP_0804_8P4R]  314.32 81.05 270 top
RR3  10K_0402_5%  [R_0402]  26.73 45.23 90 top
RR4  6.2K_0402_1%  [R_0402]  29.47 53.85 90 top
RR5  0_0402_5%  [R0402_0OHM]  21.66 52.77 90 top
RR6  0_0402_5%  [R0402_0OHM]  21.67 50.82 180 top
RR7  0_0402_5%  [R0402_0OHM]  21.67 49.8 180 top
RR8  0_0402_5%  [R0402_0OHM]  21.67 48.79 180 top
RR9  0_0402_5%  [R0402_0OHM]  23.82 53.41 90 top
RR10  0_0402_5%  [R0402_0OHM]  22.93 53.41 90 top
RR19  10K_0402_5%  [R_0402]  27.74 46.14 270 top
RT50  3.3K_0402_5%  [R_0402]  33.41 89.73 90 bottom
RT51  3.3K_0402_5%  [R_0402]  32.39 89.73 90 bottom
RT52  3.3K_0402_5%  [R_0402]  31.37 89.73 90 bottom
RT53  3.3K_0402_5%  [R_0402]  30.1 89.73 90 bottom
RT54  0_0402_5%  [R0402_0OHM]  32.9 94.96 270 top
RT55  0_0402_5%  [R0402_0OHM]  31.88 94.96 270 top
RT56  0_0402_5%  [R0402_0OHM]  30.87 94.96 270 top
RT57  0_0402_5%  [R0402_0OHM]  29.85 94.96 270 top
RT58  0_0402_5%  [R0402_0OHM]  38.04 81.48 90 bottom
RT59  0_0402_5%  [R0402_0OHM]  39.38 82.39 270 bottom
RT60  0_0402_5%  [R0402_0OHM]  38.31 79.01 180 top
RT63  0_0402_5%  [R0402_0OHM]  33.53 86.43 90 top
RT64  0_0402_5%  [R_0402]  37.39 78.12 0 top
RT65  0_0402_5%  [R_0402]  37.39 77.23 0 top
RT66  3.3K_0402_5%  [R_0402]  23.68 84.73 0 top
RT67  3.3K_0402_5%  [R_0402]  36.77 82.17 90 bottom
RT68  10K_0402_5%  [R_0402]  37.39 79.9 0 top
RT69  0_0402_5%  [R_0402]  36.62 85.29 90 top
RT70  0_0402_5%  [R0402_0OHM]  35.77 85.26 90 top
RT71  1M_0402_5%  [R_0402]  33.08 79.75 180 bottom
RT72  0_0402_5%  [R0402_0OHM]  31.82 75.79 270 top
RT73  0_0402_5%  [R0402_0OHM]  35.5 76.04 270 top
RT74  0_0402_5%  [R0402_0OHM]  33.84 78.31 0 bottom
RT75  0_0402_5%  [R_0402]  30.93 76.04 270 top
RT76  10K_0402_1%  [R_0402]  28.43 80.54 180 bottom
RT81  100K_0402_5%  [R_0402]  33.58 85.74 0 bottom
RT82  1M_0402_5%  [R_0402]  32.72 85.74 180 bottom
RT83  0_0402_5%  [R0402_0OHM]  33.61 84.85 180 bottom
RT84  0_0402_5%  [R_0402]  31.56 82.65 90 bottom
RT85  0_0402_5%  [R_0402]  30.62 82.65 90 bottom
RT86  1M_0402_5%  [R_0402]  34.61 75.79 270 top
RT87  0_0402_5%  [R_0402]  25.74 80.51 0 top
RT88  0_0402_5%  [R_0402]  25.74 81.32 0 top
RT89  0_0402_5%  [R0402_0OHM]  25.89 82.92 0 top
RT90  0_0402_5%  [R_0402]  24.59 82.89 180 top
RT92  0_0402_5%  [R0402_0OHM]  25.9 83.84 0 top
RT93  0_0402_5%  [R0402_0OHM]  23.68 83.77 0 top
RT95  100K_0402_5%  [R_0402]  28.28 86 180 top
RT96  100K_0402_5%  [R_0402]  29.14 86 0 top
RT97  0_0402_5%  [R_0402]  37.46 85.49 0 top
RT98  0_0402_5%  [R_0402]  32.71 75.79 270 top
RT99  0_0402_5%  [R0402_0OHM]  33.72 75.79 270 top
RT100  15K_0402_1%  [R_0402]  31.62 85.11 0 top
RT101  100K_0402_5%  [R_0402]  33.07 80.64 180 bottom
RT103  0_0402_5%  [R_0402]  30.04 76.04 270 top
RT104  0_0402_5%  [R0402_0OHM]  27.64 77.3 180 top
RT105  0_0402_5%  [R0402_0OHM]  29.15 76.04 270 top
RT106  10K_0402_5%  [R_0402]  33.36 82.85 180 bottom
RT107  10K_0402_5%  [R_0402]  34.69 81.72 90 bottom
RT108  0_0402_5%  [R_0402]  26.73 78.69 0 top
RT109  0_0402_5%  [R_0402]  26.72 79.58 0 top
RT110  0_0402_5%  [R_0402]  33.55 76.79 180 bottom
RT111  100K_0402_5%  [R_0402]  38.49 99.89 90 bottom
RT120  0_0402_5%  [R0402_0OHM]  15.13 96.35 180 bottom
RT121  0_0402_5%  [R0402_0OHM]  15.13 97.24 180 bottom
RT122  0_0402_5%  [R0402_0OHM]  13.64 91.08 0 top
RT123  0_0402_5%  [R0402_0OHM]  13.64 91.97 0 top
RT130  100K_0402_5%  [R_0402]  22.36 89.76 270 top
RT131  100K_0402_5%  [R_0402]  21.47 89.76 270 top
RT132  0_0402_5%  [R_0402]  19.64 89.76 270 bottom
RT133  0_0402_5%  [R_0402]  20.5 89.76 270 bottom
RT135  1K_0402_5%  [R_0402]  22.48 99.57 90 top
RT136  1K_0402_5%  [R_0402]  20.45 99.57 90 top
RT137  1K_0402_5%  [R_0402]  25.35 97.22 0 top
RT138  1K_0402_5%  [R_0402]  25.35 98.85 0 top
RT139  1K_0402_5%  [R_0402]  25.35 96.31 0 top
RT140  1K_0402_5%  [R_0402]  25.35 95.5 0 top
RT141  1K_0402_5%  [R_0402]  16.58 93.5 270 top
RT142  1K_0402_5%  [R_0402]  18.47 95.09 0 top
RT143  1K_0402_5%  [R_0402]  17.52 98.95 0 top
RT144  1K_0402_5%  [R_0402]  17.52 98.06 0 top
RT145  1K_0402_5%  [R_0402]  25.35 93.87 0 top
RT246  0_0402_5%  [R_0402]  16.96 100.81 270 bottom
RT247  1K_0402_5%  [R_0402]  18.74 99.89 90 bottom
RT248  1K_0402_5%  [R_0402]  20.52 99.89 90 bottom
RT300  1K_0402_5%  [R_0402]  25.35 92.12 0 top
RT301  20K_0402_5%  [R_0402]  25.35 91.31 0 top
RT302  20K_0402_5%  [R_0402]  25.35 98.04 0 top
RT303  20K_0402_5%  [R_0402]  19.63 99.89 90 bottom
RT304  20K_0402_5%  [R_0402]  17.52 97.17 0 top
RT305  20K_0402_5%  [R_0402]  21.4 99.57 90 top
RT306  20K_0402_5%  [R_0402]  25.35 94.68 0 top
RT307  20K_0402_5%  [R_0402]  18.47 95.95 0 top
RT308  4.7K_0402_5%  [R_0402]  17.91 91.43 180 bottom
RT339  0_0402_5%  [R_0402]  37.39 79.01 0 bottom
RT375  0_0402_5%  [R_0402]  24.59 88.71 270 top
RT376  0_0402_5%  [R_0402]  22.8 82.87 90 top
RT377  43K_0402_1%  [R_0402]  30.36 80.4 90 bottom
RT378  10K_0402_5%  [R_0402]  34.47 87.33 0 top
RT379  10K_0402_5%  [R_0402]  34.78 85.41 90 top
RT380  0_0402_5%  [R0402_0OHM]  17.53 92.59 90 top
RT393  100K_0402_5%  [R_0402]  37.39 100.25 180 bottom
RT397  0_0603_5%  [R_0603]  16.79 89.11 90 bottom
RT398  0_0603_5%  [R0603_0OHM]  27.11 100.88 180 bottom
RT405  1M_0402_5%  [R_0402]  38.36 86.33 180 top
RT406  1M_0402_5%  [R_0402]  25.89 82.11 0 top
RT407  10K_0402_5%  [R_0402]  23.68 80.79 0 top
RT410  4.7K_0402_5%  [R_0402]  24.62 89.53 180 top
RT411  4.7K_0402_5%  [R_0402]  23.75 87.8 90 top
RT412  4.7K_0402_5%  [R_0402]  26.27 90.49 180 top
RT413  4.7K_0402_5%  [R_0402]  24.62 90.37 180 top
RT414  2M_0402_5%  [R_0402]  19.64 89.76 270 top
RT415  2M_0402_5%  [R_0402]  20.5 89.76 270 top
RT416  4.7K_0402_5%  [R_0402]  17.89 90.67 270 bottom
RT417  0_0402_5%  [R_0402]  38.36 87.17 180 top
RT418  0_0402_5%  [R_0402]  24.59 81.65 180 top
RV1  4.7K_0402_5%  [R_0402]  105.99 88.02 90 bottom
RV2  4.7K_0402_5%  [R_0402]  105.1 88.02 90 bottom
RV3  100K_0402_5%  [R_0402]  92.89 82.5 0 bottom
RV4  270K_0402_5%  [R_0402]  105.54 81.79 90 bottom
RV5  47K_0402_5%  [R_0402]  103.51 81.79 90 bottom
RV6  47K_0402_5%  [R_0402]  122.94 84.35 90 bottom
RV7  100K_0402_5%  [R_0402]  103.89 88.02 90 bottom
RV8  10K_0402_5%  [R_0402]  99.19 88.8 270 bottom
RV10  470_0402_1%  [R_0402]  98.13 103.08 180 top
RV11  470_0402_1%  [R_0402]  98.99 103.08 0 top
RV12  470_0402_1%  [R_0402]  101.68 103.08 180 top
RV13  470_0402_1%  [R_0402]  102.54 103.08 0 top
RV14  470_0402_1%  [R_0402]  108.29 102.06 180 top
RV15  470_0402_1%  [R_0402]  109.15 102.06 0 top
RV16  470_0402_1%  [R_0402]  105.24 103.08 180 top
RV17  470_0402_1%  [R_0402]  106.35 103.08 0 top
RV18  10K_0402_5%  [R_0402]  110.37 100.23 90 top
RV19  10K_0402_5%  [R_0402]  116.65 106.9 270 top
RV20  1M_0402_5%  [R_0402]  115.37 111.65 0 top
RV21  20K_0402_5%  [R_0402]  114.25 108.71 90 top
RV22  2.2K_0402_5%  [R_0402]  113.11 112.27 0 bottom
RV23  2.2K_0402_5%  [R_0402]  116.02 109.89 270 bottom
RV24  5.6_0402_5%  [R_0402]  98.18 104.4 90 top
RV25  5.6_0402_5%  [R_0402]  99.19 104.4 90 top
RV26  200_0402_5%  [R_0402]  99.14 106.44 180 top
RV27  5.6_0402_5%  [R_0402]  101.73 104.4 90 top
RV28  5.6_0402_5%  [R_0402]  102.75 104.4 90 top
RV29  200_0402_5%  [R_0402]  102.7 106.42 180 top
RV30  5.6_0402_5%  [R_0402]  108.08 104.4 90 top
RV31  5.6_0402_5%  [R_0402]  109.1 104.4 90 top
RV32  200_0402_5%  [R_0402]  109.1 106.39 180 top
RV33  5.6_0402_5%  [R_0402]  105.29 104.4 90 top
RV34  5.6_0402_5%  [R_0402]  106.3 104.4 90 top
RV35  200_0402_5%  [R_0402]  106.25 106.39 180 top
RV70  100K_0402_5%  [R_0402]  110.24 96.35 0 top
RV72  100K_0402_5%  [R_0402]  107.7 97.29 90 top
RV73  1M_0402_5%  [R_0402]  99.7 101.87 90 bottom
RV75  1M_0402_5%  [R_0402]  104.78 99.45 90 top
RV76  100K_0402_5%  [R_0402]  110.24 95.46 0 top
RV78  100K_0402_5%  [R_0402]  107.69 96.41 0 top
RV79  4.7K_0402_5%  [R_0402]  94.81 99.19 90 top
RV80  4.7K_0402_5%  [R_0402]  93.92 99.19 90 top
RV81  4.7K_0402_5%  [R_0402]  94.82 97.43 180 top
RV82  4.7K_0402_5%  [R_0402]  94.82 98.32 180 top
RV83  4.7K_0402_5%  [R_0402]  94.82 96.54 180 top
RV84  4.7K_0402_5%  [R_0402]  94.82 95.65 180 top
RV85  4.7K_0402_5%  [R_0402]  94.82 93.87 180 top
RV86  4.7K_0402_5%  [R_0402]  94.82 94.76 180 top
